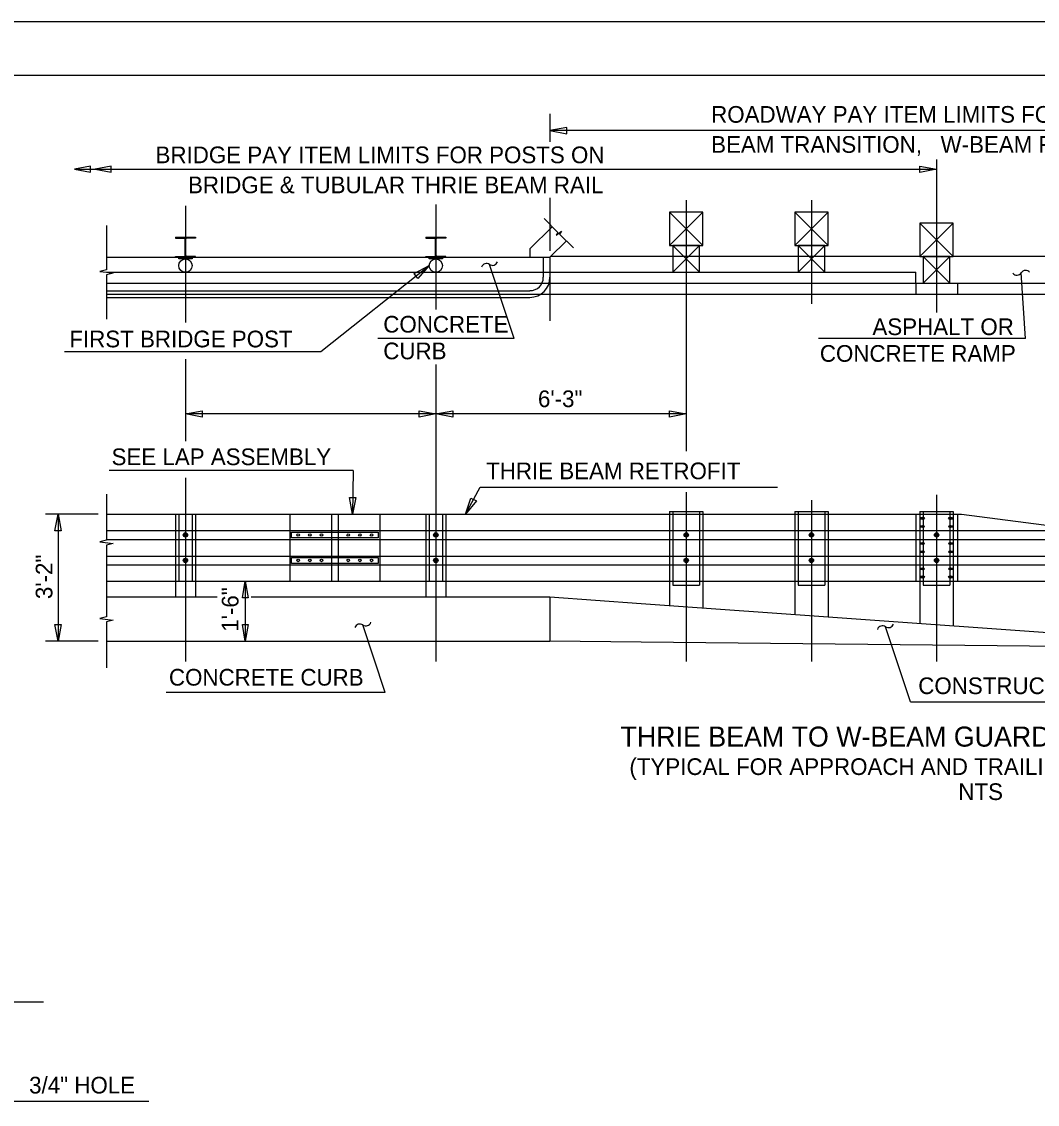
# Model space of a CAD drawing. Extents: x 0 to 22.7, y 0 to 15.7.
# Drawn here: x 11.16 to 17.5, y 7.91 to 14.67 of the extents above; entities that cross this region are included whole.
import ezdxf

# ---------------------------------------------------------------- set-up
doc = ezdxf.new("R2010")
doc.units = 0
for name, color, linetype in [('BORDER_ANNO_Cutsheet', 7, 'Continuous'), ('BRDG_ANNO_Anno-Sheet', 7, 'Continuous'), ('BRDG_ANNO_General-Notes', 7, 'Continuous'), ('BRDG_BASE_Active-Point', 7, 'Continuous'), ('BRDG_BASE_Dtlctrln', 7, 'Continuous'), ('BRDG_BASE_Hidden-Line', 7, 'Continuous'), ('BRDG_BASE_Obj-Line', 7, 'Continuous'), ('BRDG_BASE_Phtline', 7, 'Continuous'), ('BRDG_BASE_Rebar', 7, 'Continuous'), ('Default', 7, 'Continuous')]:
    doc.layers.add(name, color=color, linetype=linetype)

# ---------------------------------------------------------------- blocks, each defined once
blk = doc.blocks.new('TERM')
at = {"layer": 'Default'}
for p, q in [((-1.6, -0.267), (-1.6, 0.267)), ((-1.6, 0.267), (0, 0)), ((0, 0), (-1.6, -0.267))]:
    blk.add_line(p, q, dxfattribs=at)

msp = doc.modelspace()

# ---------------------------------------------------------------- linework, layer by layer
at = {"layer": 'BORDER_ANNO_Cutsheet'}
msp.add_lwpolyline([(0, 14.6667), (22.6667, 14.6667), (22.6667, 0), (0, 0)], close=True, dxfattribs=at)
at = {"layer": 'BRDG_ANNO_Anno-Sheet'}
msp.add_lwpolyline([(1, 14.3333), (22.3333, 14.3333), (22.3333, 0.3333), (1, 0.3333)], close=True, dxfattribs=at)
at = {"layer": 'BRDG_ANNO_General-Notes'}
for p, q in [((14.4561, 14.0907), (14.4561, 13.9164)), ((14.5611, 14.0061), (14.4561, 13.9864)), ((14.5611, 13.9667), (14.5611, 14.0061)), ((20.3134, 13.9864), (14.4561, 13.9864)), ((14.4561, 13.9864), (14.5611, 13.9667)), ((11.588, 13.7643), (11.488, 13.7456)), ((11.488, 13.7456), (16.869, 13.7456)), ((11.488, 13.7456), (11.588, 13.7268)), ((11.588, 13.7268), (11.588, 13.7643)), ((11.7172, 13.7643), (11.6172, 13.7456)), ((11.6172, 13.7456), (11.7172, 13.7268)), ((11.7172, 13.7268), (11.7172, 13.7643)), ((16.764, 13.7259), (16.764, 13.7653)), ((16.764, 13.7653), (16.869, 13.7456)), ((16.869, 13.7456), (16.764, 13.7259)), ((14.4561, 13.568), (14.4561, 13.2361)), ((13.027, 12.6071), (13.7023, 13.1439)), ((13.6078, 13.094), (13.7023, 13.1439)), ((13.7023, 13.1439), (13.6323, 13.0631)), ((14.2319, 12.6897), (14.079, 13.1515)), ((13.6323, 13.0631), (13.6078, 13.094)), ((17.4239, 12.6886), (17.3972, 13.0994)), ((14.2319, 12.6897), (13.3825, 12.6897)), ((17.4239, 12.6886), (16.1316, 12.6886)), ((11.4267, 12.6071), (13.027, 12.6071)), ((12.1815, 12.2181), (12.2865, 12.2378)), ((12.2865, 12.2378), (12.2865, 12.1984)), ((13.639, 12.1984), (13.639, 12.2378)), ((13.639, 12.2378), (13.744, 12.2181)), ((13.744, 12.2181), (13.849, 12.2378)), ((13.849, 12.2378), (13.849, 12.1984)), ((15.2015, 12.1984), (15.2015, 12.2378)), ((15.2015, 12.2378), (15.3065, 12.2181)), ((13.744, 12.2181), (12.1815, 12.2181)), ((12.2865, 12.1984), (12.1815, 12.2181)), ((13.744, 12.2181), (13.639, 12.1984)), ((15.3065, 12.2181), (13.744, 12.2181)), ((13.849, 12.1984), (13.744, 12.2181)), ((15.3065, 12.2181), (15.2015, 12.1984)), ((13.2272, 11.8649), (11.7061, 11.8649)), ((13.2272, 11.8649), (13.2229, 11.5918)), ((13.2049, 11.6971), (13.2443, 11.6965)), ((13.2229, 11.5918), (13.2049, 11.6971)), ((13.2443, 11.6965), (13.2229, 11.5918)), ((13.9298, 11.5918), (13.9622, 11.6935)), ((13.9622, 11.6935), (13.9969, 11.6749)), ((13.9969, 11.6749), (13.9298, 11.5918)), ((11.6361, 11.5918), (11.308, 11.5918)), ((11.3861, 11.5918), (11.3861, 10.8001)), ((12.5549, 11.1751), (12.5549, 10.8001)), ((13.4285, 10.4789), (13.2886, 10.9013)), ((16.7052, 10.4213), (16.5499, 10.8902)), ((11.6361, 10.8001), (11.308, 10.8001)), ((13.4285, 10.4789), (12.0604, 10.4789)), ((16.7052, 10.4213), (19.9203, 10.4213))]:
    msp.add_line(p, q, dxfattribs=at)
for points in [[(13.9298, 11.5918), (14.0208, 11.7608)], [(14.0208, 11.7608), (15.8765, 11.7608)], [(10.8351, 8.4816), (11.0244, 7.9296), (11.9532, 7.9296)]]:
    msp.add_lwpolyline(points, dxfattribs=at)
for centre, start, end in [((14.0602, 13.1245), 55.19873, 161.45893), ((14.0977, 13.1784), 235.19873, 341.45893), ((17.4247, 13.0815), 40.57666, 146.83687), ((17.3698, 13.1174), 220.57666, 326.83687), ((13.2699, 10.8744), 55.19873, 161.45893), ((13.3074, 10.9282), 235.19873, 341.45893), ((16.5312, 10.8632), 55.19873, 161.45893), ((16.5686, 10.9171), 235.19873, 341.45893)]:
    msp.add_arc(centre, 0.0328, start, end, dxfattribs=at)
at = {"layer": 'BRDG_BASE_Active-Point'}
for p, q in [((12.119, 13.3209), (12.244, 13.3209)), ((12.119, 13.3209), (12.119, 13.3157)), ((12.119, 13.3157), (12.1736, 13.3157)), ((12.244, 13.3157), (12.1893, 13.3157)), ((12.244, 13.3209), (12.244, 13.3157)), ((13.6815, 13.3209), (13.8065, 13.3209)), ((13.6815, 13.3209), (13.6815, 13.3157)), ((13.6815, 13.3157), (13.7361, 13.3157)), ((13.8065, 13.3157), (13.7518, 13.3157)), ((13.8065, 13.3209), (13.8065, 13.3157)), ((12.1789, 13.2064), (12.1789, 13.3105)), ((12.1815, 13.2584), (12.1815, 13.2584)), ((12.1841, 13.2064), (12.1841, 13.3105)), ((13.7414, 13.2064), (13.7414, 13.3105)), ((13.744, 13.2584), (13.744, 13.2584)), ((13.7466, 13.2064), (13.7466, 13.3105)), ((12.119, 13.1959), (12.119, 13.2011)), ((12.119, 13.2011), (12.1736, 13.2011)), ((12.119, 13.1959), (12.244, 13.1959)), ((12.244, 13.2011), (12.1893, 13.2011)), ((12.244, 13.1959), (12.244, 13.2011)), ((13.6815, 13.1959), (13.6815, 13.2011)), ((13.6815, 13.2011), (13.7361, 13.2011)), ((13.6815, 13.1959), (13.8065, 13.1959)), ((13.8065, 13.2011), (13.7518, 13.2011)), ((13.8065, 13.1959), (13.8065, 13.2011))]:
    msp.add_line(p, q, dxfattribs=at)
for centre, start, end in [((12.1736, 13.3105), 0, 90), ((12.1892, 13.3105), 90, 180), ((13.7361, 13.3105), 0, 90), ((13.7517, 13.3105), 90, 180), ((12.1736, 13.2064), 270, 360), ((12.1892, 13.2064), 180, 270), ((13.7361, 13.2064), 270, 360), ((13.7517, 13.2064), 180, 270)]:
    msp.add_arc(centre, 0.00521, start, end, dxfattribs=at)
at = {"layer": 'BRDG_BASE_Dtlctrln'}
for p, q in [((16.869, 13.8068), (16.869, 12.852)), ((12.1815, 13.5179), (12.1815, 12.7886)), ((13.744, 13.5246), (13.744, 12.8697)), ((15.3065, 13.5521), (15.3065, 11.9859)), ((16.0877, 13.5521), (16.0877, 12.9052)), ((12.1815, 12.5595), (12.1815, 12.0492)), ((13.744, 12.526), (13.744, 10.6736)), ((12.1815, 11.8193), (12.1815, 10.6736)), ((15.3065, 11.7305), (15.3065, 10.6736)), ((16.869, 11.7127), (16.869, 10.6736)), ((16.0877, 11.6794), (16.0877, 10.6736)), ((11.2957, 8.5469), (10.2328, 8.5469))]:
    msp.add_line(p, q, dxfattribs=at)
at = {"layer": 'BRDG_BASE_Hidden-Line'}
for centre in [(12.1813, 11.4629), (13.7439, 11.4629), (12.1813, 11.304), (13.7439, 11.304)]:
    msp.add_circle(centre, 0.00651, dxfattribs=at)
for centre in [(12.1813, 11.4629), (13.7439, 11.4629), (12.1813, 11.304), (13.7439, 11.304)]:
    msp.add_ellipse(centre, major_axis=(0, 0.00977), ratio=0.666667, dxfattribs=at)
at = {"layer": 'BRDG_BASE_Obj-Line'}
for p, q in [((14.3311, 13.2477), (14.4703, 13.3869)), ((14.5056, 13.3516), (14.419, 13.4382)), ((12.119, 13.3209), (12.244, 13.3209)), ((12.119, 13.3209), (12.119, 13.3157)), ((12.119, 13.3157), (12.1736, 13.3157)), ((12.244, 13.3157), (12.1893, 13.3157)), ((12.244, 13.3209), (12.244, 13.3157)), ((13.6815, 13.3209), (13.8065, 13.3209)), ((13.6815, 13.3209), (13.6815, 13.3157)), ((13.6815, 13.3157), (13.7361, 13.3157)), ((13.8065, 13.3157), (13.7518, 13.3157)), ((13.8065, 13.3209), (13.8065, 13.3157)), ((14.4945, 13.3332), (14.5277, 13.359)), ((14.5056, 13.3516), (14.4945, 13.3332)), ((14.5277, 13.359), (14.5166, 13.3406)), ((14.6031, 13.2541), (14.5166, 13.3406)), ((12.1789, 13.2064), (12.1789, 13.3105)), ((12.1815, 13.2584), (12.1815, 13.2584)), ((12.1841, 13.2064), (12.1841, 13.3105)), ((13.7414, 13.2064), (13.7414, 13.3105)), ((13.744, 13.2584), (13.744, 13.2584)), ((13.7466, 13.2064), (13.7466, 13.3105)), ((14.3311, 13.2477), (14.3311, 13.1959)), ((14.4561, 13.1959), (14.5587, 13.2985)), ((11.6882, 13.1959), (14.4561, 13.1959)), ((12.119, 13.1959), (12.119, 13.2011)), ((12.119, 13.2011), (12.1736, 13.2011)), ((12.119, 13.1959), (12.244, 13.1959)), ((12.244, 13.2011), (12.1893, 13.2011)), ((12.244, 13.1959), (12.244, 13.2011)), ((13.6815, 13.1959), (13.6815, 13.2011)), ((13.6815, 13.2011), (13.7361, 13.2011)), ((13.6815, 13.1959), (13.8065, 13.1959)), ((13.8065, 13.2011), (13.7518, 13.2011)), ((13.8065, 13.1959), (13.8065, 13.2011)), ((14.4145, 13.1959), (14.4145, 13.0709)), ((14.4561, 13.1959), (14.4561, 12.8003)), ((11.6882, 12.9876), (14.3311, 12.9876)), ((11.6882, 12.9459), (14.3311, 12.9459)), ((11.6882, 11.0761), (12.3801, 11.0761)), ((12.5922, 11.0761), (14.4561, 11.0761)), ((14.4561, 11.0761), (14.4561, 10.8001)), ((11.6882, 10.8001), (14.4561, 10.8001))]:
    msp.add_line(p, q, dxfattribs=at)
for points in [[(11.6882, 13.3939), (11.6882, 13.1178), (11.6465, 13.1074), (11.6882, 13.1022), (11.7298, 13.097), (11.6882, 13.0866), (11.6882, 12.8105)], [(11.6882, 11.7168), (11.6882, 11.4303), (11.6465, 11.4199), (11.7298, 11.4095), (11.6882, 11.3991), (11.6882, 11.1751), (11.6882, 10.9511), (11.6465, 10.9407), (11.7298, 10.9303), (11.6882, 10.9199), (11.6882, 10.6334)]]:
    msp.add_lwpolyline(points, dxfattribs=at)
for points in [[(12.1398, 13.1959), (12.2231, 13.1959), (12.2231, 13.1855), (12.1398, 13.1855)], [(13.7023, 13.1959), (13.7856, 13.1959), (13.7856, 13.1855), (13.7023, 13.1855)]]:
    msp.add_lwpolyline(points, close=True, dxfattribs=at)
for centre, radius in [((12.1814, 13.1439), 0.0417), ((13.7439, 13.1439), 0.0417), ((12.1813, 11.4629), 0.0137), ((13.7439, 11.4629), 0.0137), ((12.1813, 11.304), 0.0137), ((13.7439, 11.304), 0.0137)]:
    msp.add_circle(centre, radius, dxfattribs=at)
for centre, radius, start, end in [((12.1736, 13.3105), 0.00521, 0, 90), ((12.1892, 13.3105), 0.00521, 90, 180), ((13.7361, 13.3105), 0.00521, 0, 90), ((13.7517, 13.3105), 0.00521, 90, 180), ((12.1736, 13.2064), 0.00521, 270, 360), ((12.1892, 13.2064), 0.00521, 180, 270), ((13.7361, 13.2064), 0.00521, 270, 360), ((13.7517, 13.2064), 0.00521, 180, 270), ((14.3312, 13.071), 0.125, 270, 360), ((14.3312, 13.071), 0.0833, 270, 0)]:
    msp.add_arc(centre, radius, start, end, dxfattribs=at)
at = {"layer": 'BRDG_BASE_Phtline'}
for p, q in [((15.2023, 13.2689), (15.4106, 13.4772)), ((15.4106, 13.2689), (15.2023, 13.4772)), ((15.9835, 13.2689), (16.1919, 13.4772)), ((16.1919, 13.2689), (15.9835, 13.4772)), ((16.7648, 13.2011), (16.9731, 13.4095)), ((16.9731, 13.2011), (16.7648, 13.4095)), ((15.2231, 13.1022), (15.3898, 13.2689)), ((15.3898, 13.1022), (15.2231, 13.2689)), ((16.0044, 13.1022), (16.171, 13.2689)), ((16.171, 13.1022), (16.0044, 13.2689)), ((15.0244, 13.2011), (14.4614, 13.2011)), ((16.7648, 13.2011), (15.0244, 13.2011)), ((16.7856, 13.0345), (16.9523, 13.2011)), ((16.9523, 13.0345), (16.7856, 13.2011)), ((17.546, 13.2011), (16.9731, 13.2011)), ((11.6882, 13.1022), (16.7387, 13.1022)), ((16.7387, 13.0345), (16.7387, 13.1022)), ((11.6882, 13.0345), (16.7387, 13.0345)), ((16.7387, 13.0345), (16.7387, 12.9668)), ((16.7387, 13.0345), (21.8499, 13.0345)), ((16.9992, 13.0345), (16.9992, 12.9668)), ((11.6882, 12.9668), (16.7387, 12.9668)), ((16.7387, 12.9668), (21.8499, 12.9668)), ((11.6882, 11.5918), (16.7387, 11.5918)), ((12.8325, 11.5918), (12.8325, 11.1751)), ((13.0929, 11.5918), (13.0929, 11.1751)), ((13.1346, 11.5918), (13.1346, 11.1751)), ((13.395, 11.5918), (13.395, 11.1751)), ((15.2023, 11.6087), (15.4106, 11.6087)), ((15.2023, 11.6087), (15.2023, 11.5918)), ((15.2023, 11.5918), (15.2023, 11.1751)), ((15.2231, 11.6087), (15.2231, 11.5918)), ((15.2231, 11.5918), (15.2231, 11.1751)), ((15.3898, 11.6087), (15.3898, 11.5918)), ((15.3898, 11.5918), (15.3898, 11.1751)), ((15.4106, 11.6087), (15.4106, 11.5918)), ((15.4106, 11.5918), (15.4106, 11.1751)), ((15.9835, 11.6087), (16.1919, 11.6087)), ((15.9835, 11.6087), (15.9835, 11.5918)), ((15.9835, 11.5918), (15.9835, 11.1751)), ((16.0044, 11.6087), (16.0044, 11.5918)), ((16.0044, 11.5918), (16.0044, 11.1751)), ((16.171, 11.6087), (16.171, 11.5918)), ((16.171, 11.5918), (16.171, 11.1751)), ((16.1919, 11.6087), (16.1919, 11.5918)), ((16.1919, 11.5918), (16.1919, 11.1751)), ((16.7387, 11.5918), (16.7387, 11.1751)), ((16.7387, 11.5918), (17.0252, 11.5918)), ((16.7648, 11.6087), (16.9731, 11.6087)), ((16.7648, 11.6087), (16.7648, 11.5918)), ((16.7648, 11.5918), (16.7648, 11.1751)), ((16.7856, 11.6087), (16.7856, 11.5918)), ((16.7856, 11.5918), (16.7856, 11.1751)), ((16.9523, 11.6087), (16.9523, 11.5918)), ((16.9523, 11.5918), (16.9523, 11.1751)), ((16.9731, 11.6087), (16.9731, 11.5918)), ((16.9731, 11.5918), (16.9731, 11.1751)), ((16.9992, 11.5918), (16.9992, 11.1751)), ((17.0252, 11.5918), (18.2752, 11.4303)), ((11.6882, 11.4904), (16.7387, 11.4904)), ((16.7387, 11.4904), (16.9992, 11.4904)), ((16.9992, 11.4904), (17.8105, 11.4904)), ((11.6882, 11.4354), (16.7387, 11.4354)), ((16.7387, 11.4354), (16.9992, 11.4354)), ((16.9992, 11.4354), (18.2359, 11.4354)), ((11.6882, 11.3315), (16.7387, 11.3315)), ((16.7387, 11.3315), (16.9992, 11.3315)), ((16.9992, 11.3315), (18.3012, 11.3315)), ((11.6882, 11.2766), (16.7387, 11.2766)), ((16.7387, 11.2766), (16.9992, 11.2766)), ((16.9992, 11.2766), (18.3012, 11.2766)), ((11.6882, 11.1751), (16.7387, 11.1751)), ((15.2023, 11.1751), (15.2023, 11.0229)), ((15.2231, 11.1751), (15.2231, 11.1504)), ((15.2231, 11.1504), (15.3898, 11.1504)), ((15.3898, 11.1751), (15.3898, 11.1504)), ((15.4106, 11.1751), (15.4106, 11.0081)), ((15.9835, 11.1751), (15.9835, 10.9672)), ((16.0044, 11.1751), (16.0044, 11.1504)), ((16.0044, 11.1504), (16.171, 11.1504)), ((16.171, 11.1751), (16.171, 11.1504)), ((16.1919, 11.1751), (16.1919, 10.9524)), ((16.7387, 11.1751), (16.9992, 11.1751)), ((16.7648, 11.1751), (16.7648, 10.9115)), ((16.7856, 11.1751), (16.7856, 11.1504)), ((16.7856, 11.1504), (16.9523, 11.1504)), ((16.9523, 11.1751), (16.9523, 11.1504)), ((16.9731, 11.1751), (16.9731, 10.8967)), ((16.9992, 11.1751), (18.3012, 11.1751)), ((14.4561, 11.0761), (15.0244, 11.0356)), ((15.0244, 11.0356), (18.3273, 10.8001)), ((15.0244, 10.794), (14.4561, 10.8001)), ((18.3273, 10.7584), (15.0244, 10.794))]:
    msp.add_line(p, q, dxfattribs=at)
for points in [[(15.2023, 13.2689), (15.4106, 13.2689), (15.4106, 13.4772), (15.2023, 13.4772)], [(15.9835, 13.2689), (16.1919, 13.2689), (16.1919, 13.4772), (15.9835, 13.4772)], [(16.7648, 13.2011), (16.9731, 13.2011), (16.9731, 13.4095), (16.7648, 13.4095)], [(15.2231, 13.1022), (15.3898, 13.1022), (15.3898, 13.2689), (15.2231, 13.2689)], [(16.0044, 13.1022), (16.171, 13.1022), (16.171, 13.2689), (16.0044, 13.2689)], [(16.7856, 13.0345), (16.9523, 13.0345), (16.9523, 13.2011), (16.7856, 13.2011)], [(12.8429, 11.4811), (13.3846, 11.4811), (13.3846, 11.4446), (12.8429, 11.4446)], [(12.8429, 11.3222), (13.3846, 11.3222), (13.3846, 11.2858), (12.8429, 11.2858)]]:
    msp.add_lwpolyline(points, close=True, dxfattribs=at)
for centre, radius in [((12.8846, 11.4629), 0.00781), ((12.9575, 11.4629), 0.00781), ((13.0304, 11.4629), 0.00781), ((13.1971, 11.4629), 0.00781), ((13.27, 11.4629), 0.00781), ((13.3429, 11.4629), 0.00781), ((15.3064, 11.4629), 0.0137), ((15.3064, 11.4629), 0.00651), ((16.0877, 11.4629), 0.0137), ((16.0877, 11.4629), 0.00651), ((16.8689, 11.4629), 0.0137), ((16.8689, 11.4629), 0.00651), ((12.8846, 11.304), 0.00781), ((12.9575, 11.304), 0.00781), ((13.0304, 11.304), 0.00781), ((13.1971, 11.304), 0.00781), ((13.27, 11.304), 0.00781), ((13.3429, 11.304), 0.00781), ((15.3064, 11.304), 0.0137), ((15.3064, 11.304), 0.00651), ((16.0877, 11.304), 0.0137), ((16.0877, 11.304), 0.00651), ((16.8689, 11.304), 0.0137), ((16.8689, 11.304), 0.00651)]:
    msp.add_circle(centre, radius, dxfattribs=at)
for centre, major_axis, ratio in [((16.7804, 11.5664), (0.0137, 0), 0.5), ((16.7804, 11.5664), (0.00651, 0), 0.75), ((16.7804, 11.5664), (0.00651, 0), 0.5), ((16.9575, 11.5664), (0.0137, 0), 0.5), ((16.9575, 11.5664), (0.00651, 0), 0.75), ((16.9575, 11.5664), (0.00651, 0), 0.5), ((16.7804, 11.5157), (0.0137, 0), 0.5), ((16.7804, 11.5157), (0.00651, 0), 0.75), ((16.7804, 11.5157), (0.00651, 0), 0.5), ((16.9575, 11.5157), (0.0137, 0), 0.5), ((16.9575, 11.5157), (0.00651, 0), 0.75), ((16.9575, 11.5157), (0.00651, 0), 0.5), ((15.3064, 11.4629), (0, 0.00977), 0.666667), ((16.0877, 11.4629), (0, 0.00977), 0.666667), ((16.8689, 11.4629), (0, 0.00977), 0.666667), ((16.7804, 11.4094), (0.0137, 0), 0.5), ((16.7804, 11.3575), (0.0137, 0), 0.5), ((16.7804, 11.4094), (-0.00651, 0), 0.75), ((16.7804, 11.4094), (0.00651, 0), 0.5), ((16.7804, 11.3575), (-0.00651, 0), 0.75), ((16.7804, 11.3575), (0.00651, 0), 0.5), ((16.9575, 11.4094), (0.0137, 0), 0.5), ((16.9575, 11.3575), (0.0137, 0), 0.5), ((16.9575, 11.4094), (-0.00651, 0), 0.75), ((16.9575, 11.4094), (0.00651, 0), 0.5), ((16.9575, 11.3575), (-0.00651, 0), 0.75), ((16.9575, 11.3575), (0.00651, 0), 0.5), ((15.3064, 11.304), (0, 0.00977), 0.666667), ((16.0877, 11.304), (0, 0.00977), 0.666667), ((16.8689, 11.304), (0, 0.00977), 0.666667), ((16.7804, 11.2512), (0.0137, 0), 0.5), ((16.7804, 11.2512), (-0.00651, 0), 0.75), ((16.7804, 11.2512), (0.00651, 0), 0.5), ((16.9575, 11.2512), (0.0137, 0), 0.5), ((16.9575, 11.2512), (-0.00651, 0), 0.75), ((16.9575, 11.2512), (0.00651, 0), 0.5), ((16.7804, 11.2005), (0.0137, 0), 0.5), ((16.7804, 11.2005), (-0.00651, 0), 0.75), ((16.7804, 11.2005), (0.00651, 0), 0.5), ((16.9575, 11.2005), (0.0137, 0), 0.5), ((16.9575, 11.2005), (-0.00651, 0), 0.75), ((16.9575, 11.2005), (0.00651, 0), 0.5)]:
    msp.add_ellipse(centre, major_axis=major_axis, ratio=ratio, dxfattribs=at)
at = {"layer": 'BRDG_BASE_Rebar'}
for p, q in [((12.119, 11.5918), (12.119, 11.1751)), ((12.119, 11.5918), (12.244, 11.5918)), ((12.1398, 11.5918), (12.1398, 11.1751)), ((12.2231, 11.5918), (12.2231, 11.1751)), ((12.244, 11.5918), (12.244, 11.1751)), ((13.6815, 11.5918), (13.6815, 11.1751)), ((13.6815, 11.5918), (13.8065, 11.5918)), ((13.7023, 11.5918), (13.7023, 11.1751)), ((13.7856, 11.5918), (13.7856, 11.1751)), ((13.8065, 11.5918), (13.8065, 11.1751)), ((12.119, 11.1751), (12.119, 11.0761)), ((12.244, 11.1751), (12.244, 11.0761)), ((13.6815, 11.1751), (13.6815, 11.0761)), ((13.8065, 11.1751), (13.8065, 11.0761))]:
    msp.add_line(p, q, dxfattribs=at)

# ---------------------------------------------------------------- block references
at = {"layer": 'BRDG_ANNO_General-Notes', "xscale": 0.06510416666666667}
for p, yscale, rotation in [((11.3861, 11.5918), 0.0732421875, 90), ((12.5549, 11.1751), 0.06510416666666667, 90), ((11.3861, 10.8001), 0.0732421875, -90), ((12.5549, 10.8001), 0.06510416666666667, -90)]:
    msp.add_blockref('TERM', p, dxfattribs=dict(at, yscale=yscale, rotation=rotation))

# ---------------------------------------------------------------- texts
at = {"layer": 'BRDG_ANNO_General-Notes'}
for s, height, p in [('ROADWAY PAY ITEM LIMITS FOR POSTS OFF BRIDGE,   THRIE', 0.104167, (15.4621, 14.0357)), ('BEAM TRANSITION,   W-BEAM RAIL,   & CONC/ASPH RAMP', 0.104167, (15.4621, 13.8482)), ('BRIDGE PAY ITEM LIMITS FOR POSTS ON', 0.104167, (11.9946, 13.7832)), ('BRIDGE & TUBULAR THRIE BEAM RAIL', 0.104167, (12.1972, 13.5957)), ('CONCRETE', 0.10417, (13.4158, 12.726)), ('ASPHALT OR', 0.10417, (16.4687, 12.7104)), ('FIRST BRIDGE POST', 0.104167, (11.4567, 12.6339)), ('CURB', 0.10417, (13.4158, 12.5594)), ('CONCRETE RAMP', 0.104167, (16.1406, 12.5437)), ('6\'-3"', 0.10417, (14.3813, 12.2608)), ('SEE LAP ASSEMBLY', 0.104167, (11.7201, 11.8987)), ('THRIE BEAM RETROFIT', 0.104167, (14.0579, 11.8107)), ('CONCRETE CURB', 0.104167, (12.0782, 10.5226)), ('CONSTRUCT ASPHALT OR CONCRETE RAMP', 0.104167, (16.7546, 10.4696)), ('THRIE BEAM TO W-BEAM GUARDRAIL TRANSITION', 0.125, (14.8963, 10.1419)), ('(TYPICAL FOR APPROACH AND TRAILING END OF BRIDGE)', 0.104167, (14.9517, 9.9648)), ('NTS', 0.10417, (17.0047, 9.8085)), ('3/4" HOLE', 0.10417, (11.2057, 7.9768))]:
    msp.add_text(s, height=height, dxfattribs=at).set_placement(p)
for s, p in [('3\'-2"', (11.351, 11.0627)), ('1\'-6"', (12.5123, 10.8588))]:
    msp.add_text(s, height=0.10417, rotation=90, dxfattribs=at).set_placement(p)

doc.saveas('drawing.dxf')
